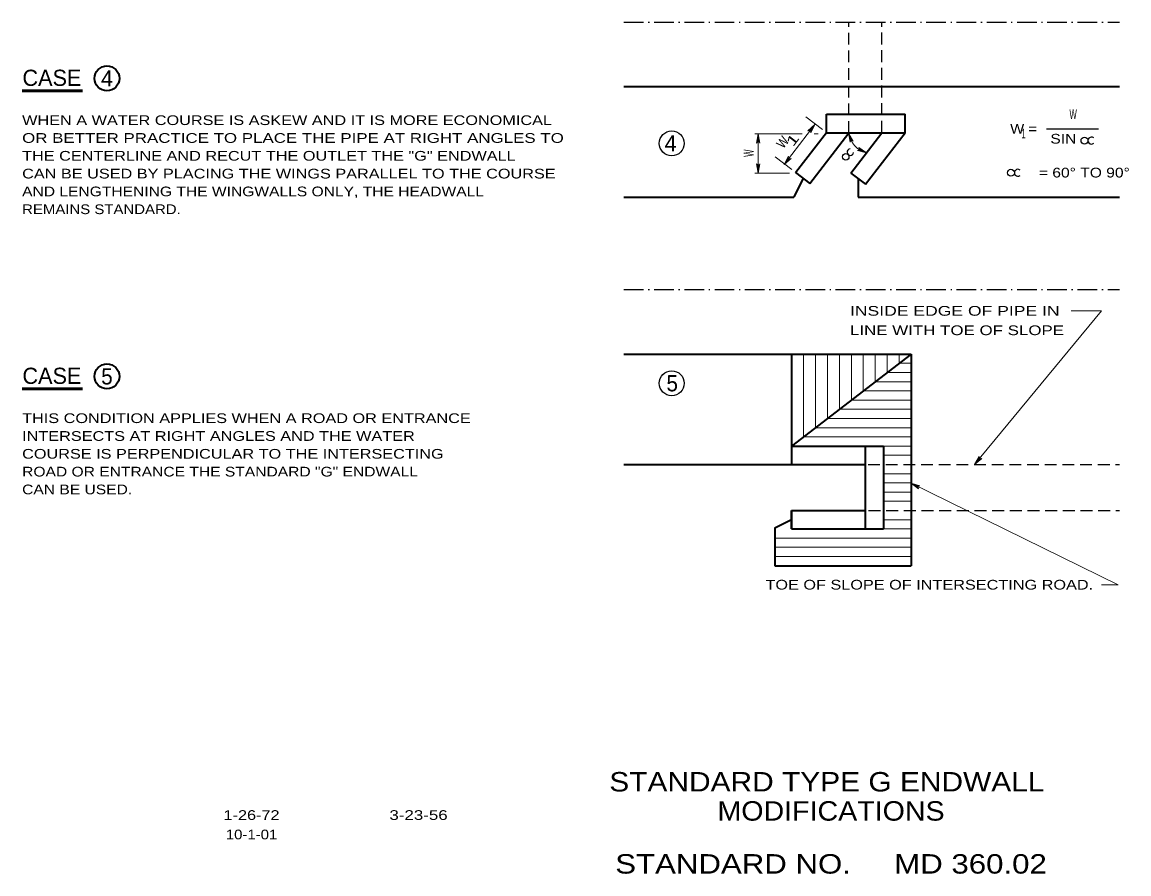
# Model space of a CAD drawing. Extents: x 134 to 247, y -59 to 103.
# Drawn here: x 133.7 to 246.4, y -59.3 to 27.5 of the extents above; entities that cross this region are included whole.
import ezdxf
from ezdxf.enums import TextEntityAlignment as Align

# ---------------------------------------------------------------- set-up
doc = ezdxf.new("R2010")
doc.units = 0
doc.header["$LTSCALE"] = 0.4
doc.linetypes.add('DOT_DASHED', pattern=[7.7, 5, -1.2, 0.3, -1.2])
doc.linetypes.add('MEDIUM_DASHED', pattern=[4.5, 3, -1.5])
for name, color, linetype, lineweight in [('1', 7, 'Continuous', 35), ('10', 7, 'Continuous', 13), ('13', 7, 'Continuous', 53), ('6', 7, 'Continuous', 13)]:
    doc.layers.add(name, color=color, linetype=linetype, lineweight=lineweight)
doc.layers.add('12', color=7, linetype='Continuous')

msp = doc.modelspace()

# ---------------------------------------------------------------- linework, layer by layer
at = {"layer": '1', "linetype": 'DOT_DASHED', "lineweight": 25}
for p, q in [((194.9967, 27.5207), (245.4598, 27.5207)), ((194.9967, 0.271), (245.4598, 0.271))]:
    msp.add_line(p, q, dxfattribs=at)
at = {"layer": '1', "linetype": 'MEDIUM_DASHED', "lineweight": 25}
for p, q in [((217.8859, 16.2381), (217.8859, 27.5207)), ((221.273, 16.2577), (221.273, 27.5301)), ((219.8722, -17.5415), (245.4598, -17.5415)), ((219.9146, -22.229), (245.4598, -22.229))]:
    msp.add_line(p, q, dxfattribs=at)
at = {"layer": '1'}
for p, q in [((194.9967, 20.9582), (245.4598, 20.9582)), ((215.6134, 18.1627), (223.6256, 18.1627)), ((215.6134, 16.2381), (215.6134, 18.1627)), ((223.6256, 16.2381), (223.6256, 18.1627)), ((212.4862, 12.1988), (215.6262, 16.2707)), ((213.919, 11.0939), (217.8859, 16.2381)), ((218.1097, 12.1557), (221.273, 16.2577)), ((219.5945, 11.0107), (223.6256, 16.2381)), ((213.2431, 11.6151), (212.2896, 9.7082)), ((212.4862, 12.1988), (213.919, 11.0939)), ((218.1097, 12.1557), (219.5945, 11.0107)), ((218.8521, 11.5832), (218.8521, 9.7082)), ((194.9967, 9.7082), (212.2896, 9.7082)), ((218.8521, 9.7082), (245.4598, 9.7082)), ((194.9967, -6.2915), (224.2528, -6.2915)), ((212.0653, -6.2915), (212.0653, -17.5415)), ((224.2528, -6.2915), (212.0653, -15.6665)), ((224.2528, -6.2915), (224.2528, -27.854)), ((212.0653, -15.6665), (221.4403, -15.6665)), ((219.5653, -15.6665), (219.5653, -24.104)), ((221.4403, -15.6665), (221.4403, -24.104)), ((194.9967, -17.5415), (212.0653, -17.5415)), ((212.0653, -17.5415), (219.5653, -17.5415)), ((212.0653, -22.229), (219.5653, -22.229)), ((212.0653, -24.104), (221.4403, -24.104)), ((210.3613, -27.854), (224.2528, -27.854))]:
    msp.add_line(p, q, dxfattribs=at)
at = {"layer": '1', "lineweight": 40}
msp.add_line((212.0653, -22.229), (212.0653, -24.104), dxfattribs=at)
at = {"layer": '1'}
for points in [[(215.6134, 16.2381), (217.8859, 16.2381), (223.6256, 16.2381)], [(212.0653, -23.1665), (210.3613, -24.0198), (210.3613, -27.854)]]:
    msp.add_lwpolyline(points, dxfattribs=at)
at = {"layer": '10'}
for p, q in [((211.3103, 13.0114), (214.4503, 17.0833)), ((215.2302, 16.576), (213.5227, 17.8928)), ((208.3437, 16.1427), (213.1474, 16.1427)), ((208.677, 16.1427), (208.677, 12.1526)), ((214.384, 16.1427), (214.7654, 16.1427)), ((212.0902, 12.5041), (210.3827, 13.8209)), ((208.3437, 12.1526), (211.8596, 12.1526)), ((243.6418, -1.8882), (230.711, -17.5433)), ((240.5496, -1.8882), (243.6418, -1.8882)), ((224.2374, -19.4479), (245.3314, -29.7926)), ((245.3314, -29.7926), (243.6482, -29.7926))]:
    msp.add_line(p, q, dxfattribs=at)
at = {"layer": '10', "lineweight": 25}
msp.add_line((238.0473, 16.6489), (243.3184, 16.6489), dxfattribs=at)
at = {"layer": '10'}
for points in [[(214.4503, 17.0833), (214.0195, 16.2385), (214.0239, 16.3257), (213.9971, 16.3932), (213.9541, 16.4399), (213.8981, 16.4696), (213.826, 16.4784), (213.7427, 16.4519), (214.4503, 17.0833), (213.826, 16.4784), (213.8981, 16.4696), (214.4503, 17.0833), (213.9541, 16.4399), (213.9971, 16.3932), (214.4503, 17.0833), (214.0239, 16.3257)], [(208.677, 16.1427), (208.8518, 15.2106), (208.802, 15.2825), (208.7395, 15.3195), (208.677, 15.3302), (208.6145, 15.3195), (208.552, 15.2825), (208.5023, 15.2106), (208.677, 16.1427), (208.552, 15.2825), (208.6145, 15.3195), (208.677, 16.1427), (208.677, 15.3302), (208.7395, 15.3195), (208.677, 16.1427), (208.802, 15.2825)], [(217.8825, 16.2375), (218.3539, 15.4147), (218.2833, 15.4662), (218.2121, 15.4806), (218.1495, 15.4702), (218.094, 15.4395), (218.0472, 15.384), (218.0238, 15.2998), (217.8825, 16.2375), (218.0472, 15.384), (218.094, 15.4395), (217.8825, 16.2375), (218.1495, 15.4702), (218.2121, 15.4806), (217.8825, 16.2375), (218.2833, 15.4662)], [(219.6988, 14.2011), (218.78, 14.4363), (218.8662, 14.451), (218.9261, 14.4921), (218.9622, 14.5442), (218.9789, 14.6054), (218.9717, 14.6777), (218.9276, 14.7531), (219.6988, 14.2011), (218.9717, 14.6777), (218.9789, 14.6054), (219.6988, 14.2011), (218.9622, 14.5442), (218.9261, 14.4921), (219.6988, 14.2011), (218.8662, 14.451)], [(211.3103, 13.0114), (211.7411, 13.8562), (211.7366, 13.769), (211.7635, 13.7015), (211.8064, 13.6548), (211.8625, 13.6251), (211.9346, 13.6163), (212.0178, 13.6428), (211.3103, 13.0114), (211.9346, 13.6163), (211.8625, 13.6251), (211.3103, 13.0114), (211.8064, 13.6548), (211.7635, 13.7015), (211.3103, 13.0114), (211.7366, 13.769)], [(208.677, 12.1526), (208.5023, 13.0846), (208.552, 13.0128), (208.6145, 12.9758), (208.677, 12.9651), (208.7395, 12.9758), (208.802, 13.0128), (208.8518, 13.0846), (208.677, 12.1526), (208.802, 13.0128), (208.7395, 12.9758), (208.677, 12.1526), (208.677, 12.9651), (208.6145, 12.9758), (208.677, 12.1526), (208.552, 13.0128)], [(230.711, -17.5433), (231.1698, -16.7134), (231.1625, -16.8004), (231.1871, -16.8688), (231.2284, -16.9169), (231.2834, -16.9484), (231.3552, -16.9596), (231.4393, -16.936), (230.711, -17.5433), (231.3552, -16.9596), (231.2834, -16.9484), (230.711, -17.5433), (231.2284, -16.9169), (231.1871, -16.8688), (230.711, -17.5433), (231.1625, -16.8004)], [(224.2374, -19.4479), (225.1512, -19.7014), (225.0648, -19.7145), (225.004, -19.7543), (224.9669, -19.8057), (224.949, -19.8665), (224.9547, -19.9389), (224.9973, -20.0152), (224.2374, -19.4479), (224.9547, -19.9389), (224.949, -19.8665), (224.2374, -19.4479), (224.9669, -19.8057), (225.004, -19.7543), (224.2374, -19.4479), (225.0648, -19.7145)]]:
    msp.add_lwpolyline(points, dxfattribs=at)
at = {"layer": '10', "lineweight": 35}
for centre in [(142.3322, 21.8002), (142.3326, -8.5645)]:
    msp.add_circle(centre, 1.2661, dxfattribs=at)
at = {"layer": '10', "lineweight": 25}
for centre, radius in [((199.8638, 15.1771), 1.2661), ((241.9104, 15.4648), 0.3542), ((217.5867, 13.8092), 0.3321), ((234.4131, 12.1788), 0.3542), ((199.8638, -9.2658), 1.2661)]:
    msp.add_circle(centre, radius, dxfattribs=at)
at = {"layer": '10'}
msp.add_arc((220.3087, 16.5734), 2.4459, 187.87808, 255.65352, dxfattribs=at)
at = {"layer": '10', "lineweight": 25}
for centre, radius, start, end in [((242.6188, 15.4648), 0.3542, 50.43484, 309.56516), ((218.0563, 14.2788), 0.3321, 95.43484, 354.56516), ((235.1215, 12.1788), 0.3542, 50.43484, 309.56516)]:
    msp.add_arc(centre, radius, start, end, dxfattribs=at)
at = {"layer": '13'}
for p, q in [((133.6927, 20.5341), (139.8322, 20.5341)), ((133.6931, -9.8306), (139.8326, -9.8306))]:
    msp.add_line(p, q, dxfattribs=at)
at = {"layer": '6'}
for p, q in [((213.284, -14.729), (213.284, -6.2915)), ((214.5028, -13.7915), (214.5028, -6.2915)), ((215.7215, -12.854), (215.7215, -6.2915)), ((216.9403, -11.9165), (216.9403, -6.2915)), ((218.159, -10.979), (218.159, -6.2915)), ((219.3778, -10.0415), (219.3778, -6.2915)), ((220.5965, -9.104), (220.5965, -6.2915)), ((221.8153, -8.1665), (221.8153, -6.2915)), ((223.034, -7.229), (223.034, -6.2915)), ((223.034, -7.229), (224.2528, -7.229)), ((221.8153, -8.1665), (224.2528, -8.1665)), ((219.3778, -10.0415), (224.2528, -10.0415)), ((220.5965, -9.104), (224.2528, -9.104)), ((218.159, -10.979), (224.2528, -10.979)), ((216.9403, -11.9165), (224.2528, -11.9165)), ((215.7215, -12.854), (224.2528, -12.854)), ((214.5028, -13.7915), (224.2528, -13.7915)), ((213.284, -14.729), (224.2528, -14.729)), ((221.4403, -15.6665), (224.2528, -15.6665)), ((221.4403, -16.604), (224.2528, -16.604)), ((221.4403, -18.479), (224.2528, -18.479)), ((221.4403, -19.4165), (224.2528, -19.4165)), ((221.4403, -20.354), (224.2528, -20.354)), ((221.4403, -21.2915), (224.2528, -21.2915)), ((221.4403, -23.1665), (224.2528, -23.1665)), ((221.4403, -24.104), (224.2528, -24.104)), ((210.3613, -25.0415), (224.2528, -25.0415)), ((210.3613, -25.979), (224.2528, -25.979)), ((210.3613, -26.9165), (224.2528, -26.9165))]:
    msp.add_line(p, q, dxfattribs=at)

# ---------------------------------------------------------------- texts
at = {"layer": '12'}
for s, width, p in [('W', 0.6, (240.7524, 17.6489)), ('W =', 1.15, (235.7094, 16.1771)), ('1', 0.55, (235.7094, 15.6771)), ('SIN', 1.2, (239.7524, 15.1539)), ('= 60° TO 90°', 1.2, (241.8917, 11.7022))]:
    msp.add_text(s, height=0.99, dxfattribs=dict(at, width=width)).set_placement(p, align=Align.CENTER)
for s, rotation, width, p in [('W', 52.363, 0.85, (211.555, 14.9879)), ('1', 52.363, 1.6, (212.5721, 15.2327)), ('W', 90, 0.6, (208.193, 14.1768))]:
    msp.add_text(s, height=0.99, rotation=rotation, dxfattribs=dict(at, width=width)).set_placement(p, align=Align.CENTER)
for s, width, p in [('INSIDE EDGE OF PIPE IN', 1.35, (218.0208, -2.3832)), ('LINE WITH TOE OF SLOPE', 1.3, (218.0208, -4.3632))]:
    msp.add_text(s, height=0.99, dxfattribs=dict(at, width=width)).set_placement(p)
at = {"layer": '12', "width": 1.25}
msp.add_text('TOE OF SLOPE OF INTERSECTING ROAD.', height=0.99, dxfattribs=at).set_placement((242.7873, -30.2876), align=Align.RIGHT)
at = {"layer": '13'}
for s, p in [('CASE', (136.728, 21.0341)), ('4', (142.3322, 20.9752)), ('4', (199.7426, 14.3521)), ('CASE', (136.7283, -9.3306))]:
    msp.add_text(s, height=1.65, dxfattribs=at).set_placement(p, align=Align.CENTER)
for s, width, p in [('WHEN A WATER COURSE IS ASKEW AND IT IS MORE ECONOMICAL', 1.25, (133.6927, 17.0441)), ('OR BETTER PRACTICE TO PLACE THE PIPE AT RIGHT ANGLES TO', 1.3, (133.6927, 15.2291)), ('THE CENTERLINE AND RECUT THE OUTLET THE "G" ENDWALL', 1.25, (133.6927, 13.4141)), ('CAN BE USED BY PLACING THE WINGS PARALLEL TO THE COURSE', 1.25, (133.6927, 11.5991)), ('AND LENGTHENING THE WINGWALLS ONLY, THE HEADWALL', 1.2, (133.6927, 9.7841)), ('REMAINS STANDARD.', 1.15, (133.6927, 7.9691)), ('THIS CONDITION APPLIES WHEN A ROAD OR ENTRANCE', 1.25, (133.6931, -13.3206)), ('INTERSECTS AT RIGHT ANGLES AND THE WATER', 1.25, (133.6931, -15.1356)), ('COURSE IS PERPENDICULAR TO THE INTERSECTING', 1.25, (133.6931, -16.9506)), ('ROAD OR ENTRANCE THE STANDARD "G" ENDWALL', 1.2, (133.6931, -18.7656)), ('CAN BE USED.', 1.2, (133.6931, -20.5806))]:
    msp.add_text(s, height=0.99, dxfattribs=dict(at, width=width)).set_placement(p)
for s, height, width, p in [('5', 1.65, 0.95, (142.3326, -9.3895)), ('5', 1.65, 0.95, (199.9116, -10.0908)), ('STANDARD TYPE G ENDWALL ', 1.98, 1.15, (216.0897, -50.8601)), ('MODIFICATIONS', 1.98, 1.1, (216.0897, -53.8301)), ('1-26-72', 0.99, 1.25, (157.0632, -53.7569)), ('3-23-56', 0.99, 1.3, (174.0737, -53.7569)), ('10-1-01', 0.99, 1.15, (157.0632, -55.7369)), ('STANDARD NO.     MD 360.02', 1.98, 1.2, (216.0897, -59.2265))]:
    msp.add_text(s, height=height, dxfattribs=dict(at, width=width)).set_placement(p, align=Align.CENTER)

doc.saveas('drawing.dxf')
